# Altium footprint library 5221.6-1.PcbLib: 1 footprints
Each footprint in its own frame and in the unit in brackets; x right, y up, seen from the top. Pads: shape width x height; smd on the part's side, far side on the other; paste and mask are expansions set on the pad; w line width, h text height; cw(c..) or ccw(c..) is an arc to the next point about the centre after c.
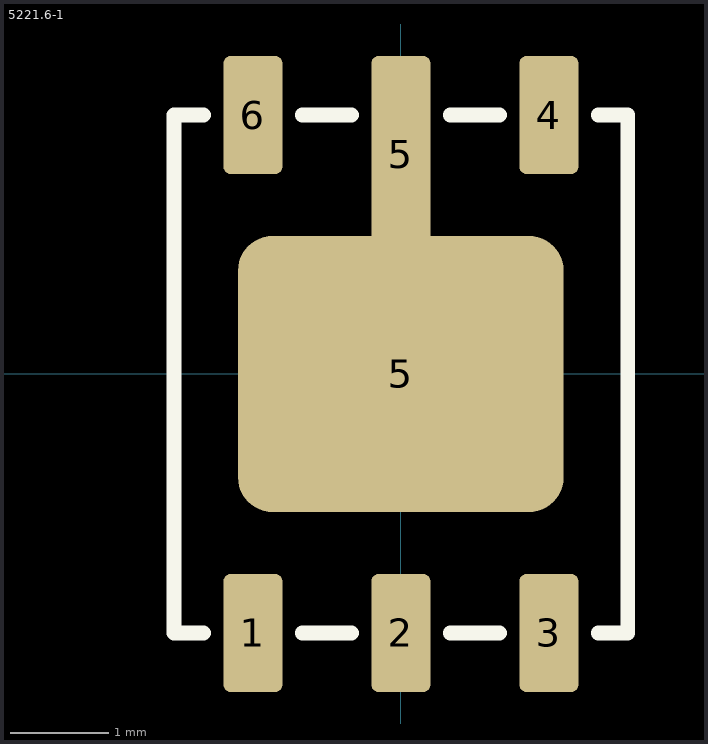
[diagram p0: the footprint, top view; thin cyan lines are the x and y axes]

## 5221.6-1 [mm] "5221.6-1 chip footprint"
height 1.7
pads (8):
  rrect25% 0.6x1.2 smd mask+0.1: 1(-1.5,-2.625) 2(0,-2.625) 3(1.5,-2.625) 4(1.5,2.625) 6(-1.5,2.625)
  rrect25% 3.3x2.8 smd mask+0.1: 5(0,0)
  rrect25% 0.6x2 smd mask+0.1: 5(0,2.225)
  round 0.5 on Top Overlay mask+0.1: ""(-3,-2.625)
Top Overlay:
  lines w0.15: -2,-2.625 -2.3,-2.625 -2.3,2.625 -2,2.625 ; -1,-2.625 -0.5,-2.625 ; -1,2.625 -0.5,2.625 ; 0.5,-2.625 1,-2.625 ; 0.5,2.625 1,2.625 ; 2,-2.625 2.3,-2.625 2.3,2.625 2,2.625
